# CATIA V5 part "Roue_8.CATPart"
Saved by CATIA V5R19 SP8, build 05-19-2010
Part number: Roue_8
Nomenclature: 70_R8
Bounding box of the stored display mesh (mm): x -3.985 to 3.985, y -3.994 to 3.994, z 0 to 2
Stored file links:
  C:\Users\rphgr\Desktop\0_Tapis_TC520B_vitesse\Roue_8.CATPart
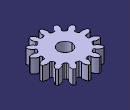
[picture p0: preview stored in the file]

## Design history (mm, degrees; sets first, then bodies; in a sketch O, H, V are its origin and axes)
External parameters (linked from other documents)
  External.Module = 0.5 mm
  External.Z = 14
  External.DiamPrimitif = 7 mm {= External.Module *External.Z}
  External.AnglePression = 20 deg
  External.x = 0
  External.DeportDenture = 0 mm {= External.x *External.Module}
  External.DiamBase = 6.5778 mm {= External.DiamPrimitif *cos(External.AnglePression )}
  External.DiamPied = 5.75 mm {= External.DiamPrimitif -2.5*External.Module +2*External.DeportDenture}
  External.DiamTete = 8 mm {= External.DiamPrimitif +2*External.Module +2*External.DeportDenture}
  External.PhiPrimitif = 0.854 deg {= atan((sin(External.ThetaPrimitif*1rad)-External.ThetaPrimitif*cos(External.ThetaPrimitif*1rad))/(cos(External.ThetaPrimitif*1rad)+External.ThetaPrimitif*sin(External.ThetaPrimitif*1rad)))}
  External.PhiTete = 4.9693 deg {= atan((sin(External.ThetaTete*1rad)-External.ThetaTete*cos(External.ThetaTete*1rad))/(cos(External.ThetaTete*1rad)+External.ThetaTete*sin(External.ThetaTete*1rad)))}
  External.PhiSymetrie = 6.4286 deg {= 180*1 deg/(2*External.Z )}
  External.CongePied = 0.19 mm {= 0.38*External.Module}
  External.AlphaCopie = 25.7143 deg {= 360*1 deg/External.Z}
  External.AlphaSymetrieCopie = 12.8571 deg {= External.AlphaCopie /2}
  External.CoeffQualiteEngrenage = 7
  External.LargeurDenture = 2 mm
  External.ThetaPrimitif = 0.36397 {= sqrt(abs((External.DiamPrimitif*External.DiamPrimitif)/(External.DiamBase *External.DiamBase )-1))}
  External.ThetaTete = 0.692207 {= sqrt(abs((External.DiamTete*External.DiamTete)/(External.DiamBase *External.DiamBase )-1) )}
  External.Di = 6.7889 mm {= (External.DiamBase +External.DiamPrimitif )/2}
  External.Thetai = 0.255358 {= sqrt(abs((External.Di*External.Di)/(External.DiamBase*External.DiamBase)-1))}
  External.Phii = 0.3061 deg {= atan((sin(External.Thetai*1rad)-External.Thetai*cos(External.Thetai*1rad))/(cos(External.Thetai*1rad)+External.Thetai*sin(External.Thetai*1rad)))}
  External.Dj = 7.5 mm {= (External.DiamTete+External.DiamPrimitif)/2}
  External.Thetaj = 0.547754 {= sqrt(abs((External.Dj*External.Dj)/(External.DiamBase*External.DiamBase)-1))}
  External.Phij = 2.6721 deg {= atan((sin(External.Thetaj*1rad)-External.Thetaj*cos(External.Thetaj*1rad))/(cos(External.Thetaj*1rad)+External.Thetaj*sin(External.Thetaj*1rad)))}
  External.Dk = 6.6834 mm {= (External.Di+External.DiamBase)/2}
  External.Thetak = 0.179851 {= sqrt(abs((External.Dk*External.Dk)/(External.DiamBase*External.DiamBase)-1))}
  External.Phik = 0.109 deg {= atan((sin(External.Thetak*1rad)-External.Thetak*cos(External.Thetak*1rad))/(cos(External.Thetak*1rad)+External.Thetak*sin(External.Thetak*1rad)))}
  External.Dl = 6.8945 mm {= (External.DiamPrimitif+External.Di)/2}
  External.Thetal = 0.31398 {= sqrt(abs((External.Dl*External.Dl)/(External.DiamBase*External.DiamBase)-1))}
  External.Phil = 0.5585 deg {= atan((sin(External.Thetal*1rad)-External.Thetal*cos(External.Thetal*1rad))/(cos(External.Thetal*1rad)+External.Thetal*sin(External.Thetal*1rad)))}
  External.Dm = 7.25 mm {= (External.Dj+External.DiamPrimitif)/2}
  External.Thetam = 0.463476 {= sqrt(abs((External.Dm*External.Dm)/(External.DiamBase*External.DiamBase)-1))}
  External.Phim = 1.6886 deg {= atan((sin(External.Thetam*1rad)-External.Thetam*cos(External.Thetam*1rad))/(cos(External.Thetam*1rad)+External.Thetam*sin(External.Thetam*1rad)))}
  External.Dn = 7.75 mm {= (External.DiamTete+External.Dj)/2}
  External.Thetan = 0.623015 {= sqrt(abs((External.Dn*External.Dn)/(External.DiamBase*External.DiamBase)-1))}
  External.Phin = 3.7726 deg {= atan((sin(External.Thetan*1rad)-External.Thetan*cos(External.Thetan*1rad))/(cos(External.Thetan*1rad)+External.Thetan*sin(External.Thetan*1rad)))}
  External.DiametreAlesage = 2 mm
Body1 (main body)
  Sketch1 on xy-plane, origin (0, 0, 0), H (1, 0, 0), V (0, 1, 0)
    construction circle A1 centre (0, 0) radius 3.5
    construction circle A2 centre (0, 0) radius 3.2889
    construction circle A3 centre (0, 0) radius 2.875
    construction circle A4 centre (0, 0) radius 4
    point P1 (3.2889, 0)
    construction line L1 (3.2889, 0) -> (0, 0)
    point P2 (3.4996, 0.0522)
    construction line L2 (3.4996, 0.0522) -> (0, 0)
    point P3 (3.985, 0.3465)
    construction line L3 (3.985, 0.3465) -> (0, 0)
    construction line L4 (3.2889, 0) -> (3.2889, 3.9367)
    point P4 (3.2889, 0)
    point P6 (3.0782, 0.0522)
    construction line L5 (3.985, 0.3465) -> (3.4996, 0.0522)
    point P7 (3.7423, 0.1993)
    point P8 (2.8356, 0.1993)
    spline S1 through (2.8356, 0.1993) (3.0782, 0.0522) (3.2889, 0) (3.3417, 0.0064) (3.3944, 0.0181) (3.4471, 0.0336) (3.4996, 0.0522) (3.6234, 0.1068) (3.7459, 0.1748) (3.8666, 0.255) (3.985, 0.3465)
    construction line L6 (0, 0) -> (5.2319, 0.6686)
    spline S2 through (2.7946, 0.5202) (2.9924, 0.7236) (3.1832, 0.8271) (3.2359, 0.8342) (3.2899, 0.8361) (3.3447, 0.8343) (3.4003, 0.8296) (3.5338, 0.8078) (3.6695, 0.7728) (3.8065, 0.7256) (3.944, 0.6668)
    arc A5 centre (3.0614, -0.1486) radius 0.19 from (3.1316, 0.028) to (2.8716, -0.1393) ccw
    point P11 (2.8716, -0.1393)
    arc A6 centre (0, 0) radius 4 from (3.985, 0.3465) to (3.944, 0.6668) ccw
    point P13 (3.944, 0.6668)
    arc A7 centre (2.9257, 0.9137) radius 0.19 from (2.7443, 0.857) to (3.038, 0.7604) ccw
    point P15 (2.7443, 0.857)
    construction line L7 (0, 0) -> (4.0213, 1.4748)
    construction line L8 (0, 0) -> (5.1016, -0.4979)
    point P19 (2.6992, 0.9899)
    arc A8 centre (0, 0) radius 2.875 from (2.7443, 0.857) to (2.6992, 0.9899) ccw
    point P20 (2.8614, -0.2793)
    arc A9 centre (0, 0) radius 2.875 from (2.8614, -0.2793) to (2.8716, -0.1393) ccw
    line L9 (2.6992, 0.9899) -> (0, 0)
    line L10 (2.8614, -0.2793) -> (0, 0)
    construction circle A10 centre (0, 0) radius 3.3945
    construction line L11 (0, 0) -> (2.5698, 0.0137)
    point P22 (3.3944, 0.0181)
    construction circle A11 centre (0, 0) radius 3.75
    construction line L12 (0, 0) -> (4.0147, 0.1874)
    point P24 (3.7459, 0.1748)
    point P25 (3.7459, 0.1748)
    point P26 (3.6695, 0.7728)
    point P27 (3.2899, 0.8361)
    construction circle A12 centre (0, 0) radius 3.3417
    construction line L13 (0, 0) -> (48.2618, 0.0918)
    point P29 (3.2359, 0.8342)
    construction line L14 (0, 0) -> (63.4624, 8.1101)
    point P31 (3.3417, 0.0064)
    construction circle A13 centre (0, 0) radius 3.4472
    construction line L15 (0, 0) -> (57.3607, 0.5591)
    point P33 (3.4471, 0.0336)
    point P34 (3.3447, 0.8343)
    construction circle A14 centre (0, 0) radius 3.625
    construction line L16 (0, 0) -> (65.6822, 1.9364)
    point P36 (3.6234, 0.1068)
    point P37 (3.5338, 0.8078)
    construction circle A15 centre (0, 0) radius 3.875
    axis line L17 (0, 0) -> (59.2224, 3.9051)
    point P39 (3.8065, 0.7256)
    point P40 (3.8666, 0.255)
    point P42 (2.8356, 0.1993)
    point P43 (3.0782, 0.0522)
    point P44 (3.2889, 0)
    point P45 (3.4996, 0.0522)
    point P46 (3.985, 0.3465)
    point P47 (3.944, 0.6668)
    point P48 (2.7946, 0.5202)
    point P49 (3.4003, 0.8296)
    point P50 (3.1832, 0.8271)
    point P51 (2.9924, 0.7236)
    point P52 (3.3944, 0.0181)
    point P53 (3.7459, 0.1748)
    point P54 (3.2899, 0.8361)
    point P55 (3.6695, 0.7728)
    point P56 (3.3417, 0.0064)
    point P57 (3.2359, 0.8342)
    point P58 (3.4471, 0.0336)
    point P59 (3.3447, 0.8343)
    point P60 (3.6234, 0.1068)
    point P61 (3.5338, 0.8078)
    point P62 (3.8666, 0.255)
    point P63 (3.8065, 0.7256)
    radius A1 = 3.5 {= External.DiamPrimitif /2}
    radius A2 = 3.2889 {= External.DiamBase /2}
    radius A3 = 2.875 {= External.DiamPied /2}
    radius A4 = 4 {= External.DiamTete /2}
    angle L2 L1 = 0.854 {= External.PhiPrimitif}
    angle L3 L1 = 4.9693 {= External.PhiTete}
    angle L4 L1 = 90
    radius A5 = 0.19 {= External.CongePied}
    radius A7 = 0.19 {= External.CongePied}
    angle L7 L6 = 12.8571 {= External.AlphaSymetrieCopie}
    angle L2 L6 = 6.4286 {= External.PhiSymetrie}
    radius A10 = 3.3945 {= External.Di /2}
    angle L11 L1 = 0.3061 {= External.Phii}
    radius A11 = 3.75 {= External.Dj /2}
    angle L12 L1 = 2.6721 {= External.Phij}
    radius A12 = 3.3417 {= External.Dk/2}
    angle L13 L1 = 0.109 {= External.Phik}
    angle L14 L2 = 6.4286 {= External.PhiSymetrie}
    radius A13 = 3.4472 {= External.Dl /2}
    angle L15 L1 = 0.5585 {= External.Phil}
    radius A14 = 3.625 {= External.Dm /2}
    angle L16 L1 = 1.6886 {= External.Phim}
    radius A15 = 3.875 {= External.Dn/2}
    angle L17 L1 = 3.7726 {= External.Phin}
    coincidence: P1 A2, P1 H, P2 A1, P3 A4, P4 A2, P7 L5, P42 P8, P43 P6, P44 P1, P45 L5, P45 L2, P46 L5, P46 L3, P11 A3, P47 P13, P15 A3, P19 L7, P19 A3, P20 L8, P20 A3, P3 P46, P22 L11, P22 A10, P52 P22, P24 L12, P24 A11, P53 P24, P25 P53, P54 P27, P55 P26, P31 L13, P31 A12, P56 P31, P57 P29, P33 L15, P33 A13, P58 P33, P59 P34, P36 L16, P36 A14, P60 P36, P61 P37, P40 L17, P40 A15, P62 P40, P63 P39, O L9, O L10
    horizontal: L1 H
    tangency: L4 A2, A5 A3, A5 S1, A7 A3, A7 S2, A8 A5, A9 A5
    symmetry: P6 P2 L4, P8 P7 L4, P46 P47 L6, P42 P48 L6, P45 P49 L6, P44 P50 L6, P43 P51 L6, L8 L7 L6, P26 P25 L6, P27 P22 L6, P29 P31 L14, P34 P33 L14, P37 P36 L14, P39 P40 L14
    midpoint: P7 L5
    parallelism: L9 L7, L10 L8
    concentricity: A10 A2, A11 A1
  Pad1: profile Sketch1, direction (0, 0, 1), length 2 {= External.LargeurDenture}
  CircPattern1 "Roue Dentée": of Pad1, instances 14 {= External.Z}, angular step 25.7143 {= External.AlphaCopie}, axis from Z axis
  Body2
    Sketch2 on xy-plane, origin (0, 0, 0), H (1, 0, 0), V (0, 1, 0)
      circle A1 centre (0, 0) radius 1
      radius A1 = 1 {= External.DiametreAlesage /2}
    Pad2: profile Sketch2, direction (0, 0, 1), length 4 {= 2*External.LargeurDenture}
  Remove1: tool Body2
